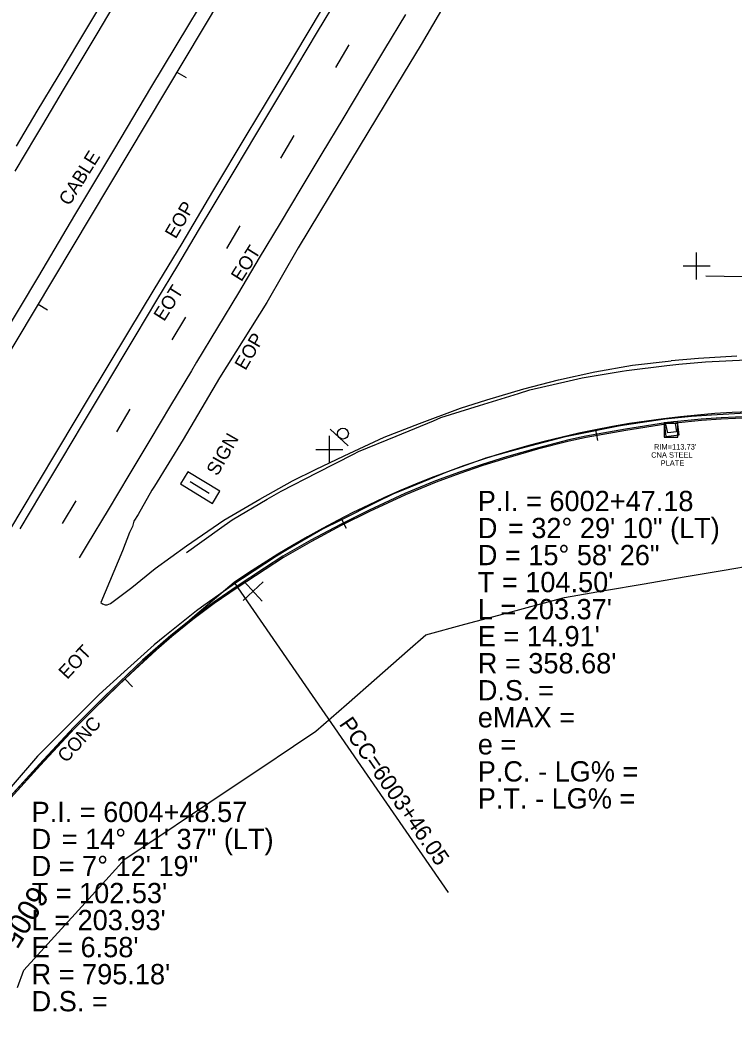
# Model space of a CAD drawing. Extents: x 2132221 to 2141942, y 535736 to 547298.
# Drawn here: x 2138362.7 to 2138626.8, y 540874.9 to 541243.7 of the extents above; entities that cross this region are included whole.
import ezdxf

# ---------------------------------------------------------------- set-up
doc = ezdxf.new("R2010")
doc.units = 0
for name, color, linetype in [('RD_EX_BldgApp', 7, 'Continuous'), ('RD_EX_BldgApp_txCode', 7, 'Continuous'), ('RD_EX_Conc', 7, 'Continuous'), ('RD_EX_Conc_txCode', 7, 'Continuous'), ('RD_EX_DR_Inlet', 7, 'Continuous'), ('RD_EX_DR_Inlet_txCode', 7, 'Continuous'), ('RD_EX_GuardRail', 7, 'Continuous'), ('RD_EX_GuardRail_txCode', 7, 'Continuous'), ('RD_EX_Misc', 7, 'Continuous'), ('RD_EX_Misc_txCode', 7, 'Continuous'), ('RD_EX_Road', 7, 'Continuous'), ('RD_EX_Road_txCode', 7, 'Continuous'), ('RD_EX_VEG', 7, 'Continuous'), ('RD_HC_Cl', 7, 'Continuous'), ('RD_HC_Data', 7, 'Continuous'), ('RD_HC_Data_Tic', 7, 'Continuous'), ('RD_HC_TX_Sta50', 7, 'Continuous')]:
    doc.layers.add(name, color=color, linetype=linetype)

msp = doc.modelspace()

# ---------------------------------------------------------------- linework, layer by layer
at = {"layer": 'RD_EX_BldgApp'}
for p, q in [((2138477.44, 541092.25), (2138484.05, 541086.14)), ((2138432.61, 541068.5), (2138425.63, 541072.81))]:
    msp.add_line(p, q, dxfattribs=at)
msp.add_circle((2138482.13, 541090.67), 2, dxfattribs=at)
at = {"layer": 'RD_EX_Conc'}
for points in [[(2138601.47, 541094.16), (2138586.73, 541091.87), (2138572.1, 541089.17), (2138565.81, 541087.82), (2138554.08, 541084.86), (2138542.78, 541081.62), (2138533.8, 541078.82), (2138525.35, 541075.89), (2138516.59, 541072.73), (2138505.28, 541068.05), (2138492, 541061.89), (2138481.51, 541056.64), (2138470.51, 541050.81), (2138460.15, 541044.88), (2138453.35, 541040.46), (2138442.96, 541033.57), (2138434.51, 541027.78), (2138426.64, 541021.86), (2138418.82, 541015.58), (2138408.34, 541006.53), (2138394.3, 540993.09), (2138382.82, 540981.59), (2138370.25, 540968.06), (2138359.38, 540956.01)], [(2138632.59, 541096.55), (2138622.03, 541095.99), (2138614.66, 541095.5), (2138604.96, 541094.58), (2138605.42, 541091.3), (2138602.25, 541090.92), (2138601.47, 541094.16)]]:
    msp.add_lwpolyline(points, dxfattribs=at)
msp.add_lwpolyline([(2138422.06, 541072.06), (2138433.88, 541064.86), (2138436.59, 541069.32), (2138424.78, 541076.53)], close=True, dxfattribs=at)
at = {"layer": 'RD_EX_DR_Inlet'}
for p, q in [((2138606.48, 541090.24), (2138605.89, 541095.2)), ((2138605.97, 541089.35), (2138605.97, 541094.35))]:
    msp.add_line(p, q, dxfattribs=at)
for points in [[(2138606.48, 541090.24), (2138605.89, 541095.2), (2138600.92, 541094.6), (2138601.52, 541089.64)], [(2138605.97, 541089.35), (2138605.97, 541094.35), (2138600.97, 541094.35), (2138600.97, 541089.35)]]:
    msp.add_lwpolyline(points, close=True, dxfattribs=at)
at = {"layer": 'RD_EX_GuardRail'}
for points in [[(2138439.29, 541265.65), (2138425.02, 541241.91), (2138410.99, 541218.57), (2138397.65, 541196.1), (2138382.86, 541171.47), (2138369.49, 541148.92), (2138347.62, 541112.4), (2138333.26, 541088.16), (2138322.29, 541069.44), (2138320.66, 541066.74)], [(2138741.71, 541128.04), (2138728.38, 541131.85), (2138716.59, 541135.4), (2138704.82, 541138.92), (2138698.54, 541141.16), (2138694.8, 541142.81), (2138691.38, 541143.5), (2138680.12, 541145.01), (2138661.79, 541146.7), (2138649.51, 541147.76), (2138636.49, 541148.52), (2138616.27, 541148.94)]]:
    msp.add_lwpolyline(points, dxfattribs=at)
at = {"layer": 'RD_EX_Misc'}
for p, q in [((2138479.48, 541226.01), (2138484.48, 541234.4)), ((2138459.13, 541192.53), (2138464.12, 541200.92)), ((2138439.19, 541159.11), (2138444.18, 541167.49)), ((2138612.89, 541147.68), (2138612.89, 541157.68)), ((2138607.89, 541152.68), (2138617.89, 541152.68)), ((2138419.01, 541125.38), (2138424.01, 541133.77)), ((2138398.5, 541091.29), (2138403.49, 541099.68)), ((2138477.14, 541079.84), (2138477.14, 541089.84)), ((2138472.14, 541084.84), (2138482.14, 541084.84)), ((2138378.43, 541057.42), (2138383.43, 541065.81)), ((2138445.23, 541029), (2138452.57, 541035.79)), ((2138445.51, 541036.07), (2138452.29, 541028.72))]:
    msp.add_line(p, q, dxfattribs=at)
for points in [[(2138362.74, 541055.45), (2138370.44, 541068.32), (2138378.14, 541081.19), (2138385.84, 541094.06), (2138393.54, 541106.93), (2138401.25, 541119.8), (2138405.64, 541127.15), (2138413.34, 541140.02), (2138421.05, 541152.9), (2138428.75, 541165.77), (2138434.54, 541175.45), (2138442.25, 541188.32), (2138449.95, 541201.2), (2138457.33, 541213.54), (2138465.03, 541226.41), (2138472.74, 541239.28), (2138480.44, 541252.15)], [(2138361.41, 541196.98), (2138369.11, 541209.86), (2138376.81, 541222.73), (2138384.51, 541235.6), (2138392.22, 541248.47)], [(2138505.22, 541245.66), (2138497.5, 541232.8), (2138489.78, 541219.94), (2138482.06, 541207.07), (2138474.34, 541194.21), (2138466.61, 541181.35), (2138458.89, 541168.49), (2138451.17, 541155.63), (2138443.45, 541142.77), (2138435.73, 541129.91), (2138428.01, 541117.05), (2138426.14, 541113.93), (2138418.42, 541101.07), (2138410.7, 541088.21), (2138402.98, 541075.35), (2138395.26, 541062.49), (2138387.54, 541049.63), (2138384.63, 541044.78)], [(2138424.25, 541046.68), (2138436.46, 541055.4), (2138441.2, 541058.78), (2138454.13, 541066.38), (2138459.34, 541069.44), (2138472.69, 541076.27), (2138486.04, 541083.11), (2138487.9, 541084.05), (2138501.77, 541089.75), (2138515.64, 541095.45), (2138518.37, 541096.57), (2138532.68, 541101.07), (2138546.99, 541105.56), (2138551.18, 541106.88), (2138565.8, 541110.22), (2138570.58, 541111.31), (2138585.37, 541113.78), (2138587.04, 541114.06), (2138601.93, 541115.87), (2138606.32, 541116.4), (2138616.21, 541117.17), (2138631.19, 541117.98)], [(2138633.35, 541098.38), (2138618.38, 541097.43), (2138611.04, 541096.97), (2138601.14, 541095.98), (2138586.3, 541093.81), (2138584.07, 541093.48), (2138569.36, 541090.52), (2138563.75, 541089.39), (2138549.28, 541085.47), (2138534.8, 541081.54), (2138534.63, 541081.49), (2138520.83, 541076.58), (2138506.97, 541070.85), (2138500.59, 541068.21), (2138494.51, 541065.37), (2138481.13, 541058.59), (2138474.62, 541055.3), (2138461.65, 541047.76), (2138457.55, 541045.37), (2138445.03, 541037.11), (2138442.05, 541035.14), (2138429.8, 541026.49), (2138427.92, 541025.17), (2138416.28, 541015.71), (2138412.36, 541012.53), (2138401.21, 541002.5), (2138392, 540994.22), (2138381.41, 540983.6), (2138370.81, 540972.98), (2138369.23, 540971.4), (2138359.39, 540960.08)]]:
    msp.add_lwpolyline(points, dxfattribs=at)
at = {"layer": 'RD_EX_Road'}
for points in [[(2138359.33, 541055.59), (2138368.45, 541070.89), (2138377.42, 541085.87), (2138387.68, 541103), (2138403, 541128.4), (2138412.33, 541143.94), (2138422.62, 541161), (2138434.02, 541180.21), (2138446.76, 541201.43), (2138457.39, 541219.13), (2138468.55, 541237.79), (2138481.36, 541259.3)], [(2138524.81, 541258.27), (2138511.1, 541234.63), (2138497.78, 541212.69), (2138484.87, 541191.4), (2138465.52, 541159.42), (2138453.97, 541139.16), (2138436.48, 541111.24), (2138423, 541088.46), (2138412.42, 541071.17), (2138411.42, 541069.69), (2138406.4, 541060.73), (2138404.86, 541058.27), (2138404.33, 541056.29), (2138403.21, 541054.1), (2138400.59, 541047.3), (2138392.56, 541028.15), (2138393.16, 541027.7), (2138394.19, 541027.36), (2138394.93, 541027.31), (2138396.13, 541027.81)], [(2138360.87, 541187.69), (2138368.57, 541200.56), (2138371.16, 541204.89), (2138378.82, 541217.79), (2138383.47, 541225.63), (2138391.2, 541238.48), (2138397.19, 541248.45)], [(2138627.8, 541119.25), (2138613.59, 541118.49), (2138603.56, 541117.55)], [(2138396.13, 541027.81), (2138404.01, 541033.72), (2138412.67, 541040.74), (2138424.34, 541049.12), (2138438.04, 541058.6), (2138451.39, 541066.41), (2138463.53, 541073.24), (2138471.93, 541077.37), (2138482.64, 541082.42), (2138497.32, 541089.29), (2138510.41, 541094.41), (2138525.58, 541100.05), (2138535.34, 541103.17), (2138549.03, 541107.24), (2138561.8, 541110.59), (2138575.27, 541113.56), (2138589.24, 541116.02), (2138603.56, 541117.55)], [(2138601.39, 541094.65), (2138586.65, 541092.37), (2138572, 541089.66), (2138565.69, 541088.31), (2138553.95, 541085.34), (2138542.63, 541082.09), (2138533.64, 541079.3), (2138525.18, 541076.37), (2138516.41, 541073.2), (2138505.07, 541068.51), (2138491.79, 541062.34), (2138481.28, 541057.09), (2138470.27, 541051.25), (2138459.89, 541045.3), (2138453.07, 541040.88), (2138442.68, 541033.98), (2138434.22, 541028.18), (2138426.33, 541022.26), (2138418.5, 541015.97), (2138408, 541006.9), (2138393.95, 540993.44), (2138382.46, 540981.93), (2138369.88, 540968.4), (2138359, 540956.34)], [(2138601.39, 541094.65), (2138601.92, 541094.72), (2138604.39, 541095.02)], [(2138632.57, 541097.05), (2138622, 541096.49), (2138614.62, 541096), (2138604.61, 541095.05), (2138604.39, 541095.02)]]:
    msp.add_lwpolyline(points, dxfattribs=at)
at = {"layer": 'RD_EX_VEG'}
msp.add_lwpolyline([(2138361.82, 540885.85), (2138364.15, 540892.22), (2138374.24, 540903.32), (2138384.32, 540914.42), (2138394.41, 540925.52), (2138401.54, 540933.37), (2138414.01, 540941.71), (2138426.47, 540950.05), (2138438.94, 540958.4), (2138451.41, 540966.74), (2138463.87, 540975.08), (2138472.12, 540980.6), (2138483.4, 540990.49), (2138494.68, 541000.38), (2138505.95, 541010.27), (2138512.72, 541016.21), (2138527.2, 541020.13), (2138541.67, 541024.05), (2138556.15, 541027.98), (2138564, 541030.1), (2138578.79, 541032.62), (2138593.57, 541035.15), (2138608.36, 541037.67), (2138623.15, 541040.19), (2138634.51, 541042.13)], dxfattribs=at)
at = {"layer": 'RD_HC_Cl'}
msp.add_line((2139719.79, 543396.28), (2136851.48, 538600.7), dxfattribs=at)
for centre, radius, start, end in [((2138645.58, 540740.31), 358.68, 92.103, 124.5891), ((2138948.08, 540422.28), 795.18, 129.53037, 144.22397)]:
    msp.add_arc(centre, radius, start, end, dxfattribs=at)
at = {"layer": 'RD_HC_Data'}
msp.add_line((2138441.96, 541035.59), (2138521.03, 540920.92), dxfattribs=at)
at = {"layer": 'RD_HC_Data_Tic'}
for p, q in [((2138420.74, 541224.38), (2138424.18, 541222.32)), ((2138369.41, 541138.56), (2138372.85, 541136.5)), ((2138575.54, 541092.09), (2138576.32, 541088.16)), ((2138481.44, 541059.23), (2138483.27, 541055.67)), ((2138401.54, 540999.86), (2138404.29, 540996.96))]:
    msp.add_line(p, q, dxfattribs=at)

# ---------------------------------------------------------------- texts
at = {"layer": 'RD_EX_BldgApp_txCode'}
msp.add_text('SIGN', height=5, rotation=60.4283, dxfattribs=at).set_placement((2138435.72, 541074.72))
at = {"layer": 'RD_EX_Conc_txCode'}
msp.add_text('CONC', height=5, rotation=47.6778, dxfattribs=at).set_placement((2138379.79, 540968.64))
at = {"layer": 'RD_EX_DR_Inlet_txCode'}
for s, p in [("RIM=113.73'", (2138597.14, 541084.78)), ('CNA STEEL', (2138596.1, 541081.78)), ('PLATE', (2138599.61, 541078.78))]:
    msp.add_text(s, height=2, dxfattribs=at).set_placement(p)
at = {"layer": 'RD_EX_GuardRail_txCode'}
msp.add_text('CABLE', height=5, rotation=57.9884, dxfattribs=at).set_placement((2138380.95, 541174.63))
at = {"layer": 'RD_EX_Misc_txCode'}
for rotation, p in [(57.7697, (2138444.58, 541146.56)), (57.7697, (2138415.99, 541131.89)), (46.9795, (2138380.14, 540999.52))]:
    msp.add_text('EOT', height=5, rotation=rotation, dxfattribs=at).set_placement(p)
at = {"layer": 'RD_EX_Road_txCode'}
for p in [(2138420.29, 541162.42), (2138446.07, 541113.77)]:
    msp.add_text('EOP', height=5, rotation=59.7475, dxfattribs=at).set_placement(p)
at = {"layer": 'RD_HC_Data'}
for s, p in [('P.I. = 6002+47.18', (2138532, 541062)), ('D', (2138532, 541052)), ('    = 32%%d 29\' 10" (LT)', (2138532, 541052)), ('D = 15%%d 58\' 26"', (2138532, 541042)), ("T = 104.50'", (2138532, 541032)), ("L = 203.37'", (2138532, 541022)), ("E = 14.91'", (2138532, 541012)), ("R = 358.68'", (2138532, 541002)), ('D.S. = ', (2138532, 540992)), ('eMAX = ', (2138532, 540982)), ('e = ', (2138532, 540972)), ('P.C. - LG% = ', (2138532, 540962)), ('P.T. - LG% = ', (2138532, 540952)), ('P.I. = 6004+48.57', (2138367, 540947)), ('D', (2138367, 540937)), ('    = 14%%d 41\' 37" (LT)', (2138367, 540937)), ('D = 7%%d 12\' 19"', (2138367, 540927)), ("T = 102.53'", (2138367, 540917)), ("L = 203.93'", (2138367, 540907)), ("E = 6.58'", (2138367, 540897)), ("R = 795.18'", (2138367, 540887)), ('D.S. = ', (2138367, 540877))]:
    msp.add_text(s, height=7.5, dxfattribs=at).set_placement(p)
msp.add_text('PCC=6003+46.05', height=6, rotation=304.5891, dxfattribs=at).set_placement((2138480.5, 540983.22))
at = {"layer": 'RD_HC_TX_Sta50'}
msp.add_text('6005', height=8, rotation=239.1157, dxfattribs=at).set_placement((2138366.99, 540924.1))

doc.saveas('drawing.dxf')
